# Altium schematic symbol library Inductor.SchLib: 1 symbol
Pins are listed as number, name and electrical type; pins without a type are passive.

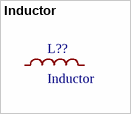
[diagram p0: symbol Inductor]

## Inductor
designator L??
footprint IND-SMD_L4.1-W3.2
pins: 1, 2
